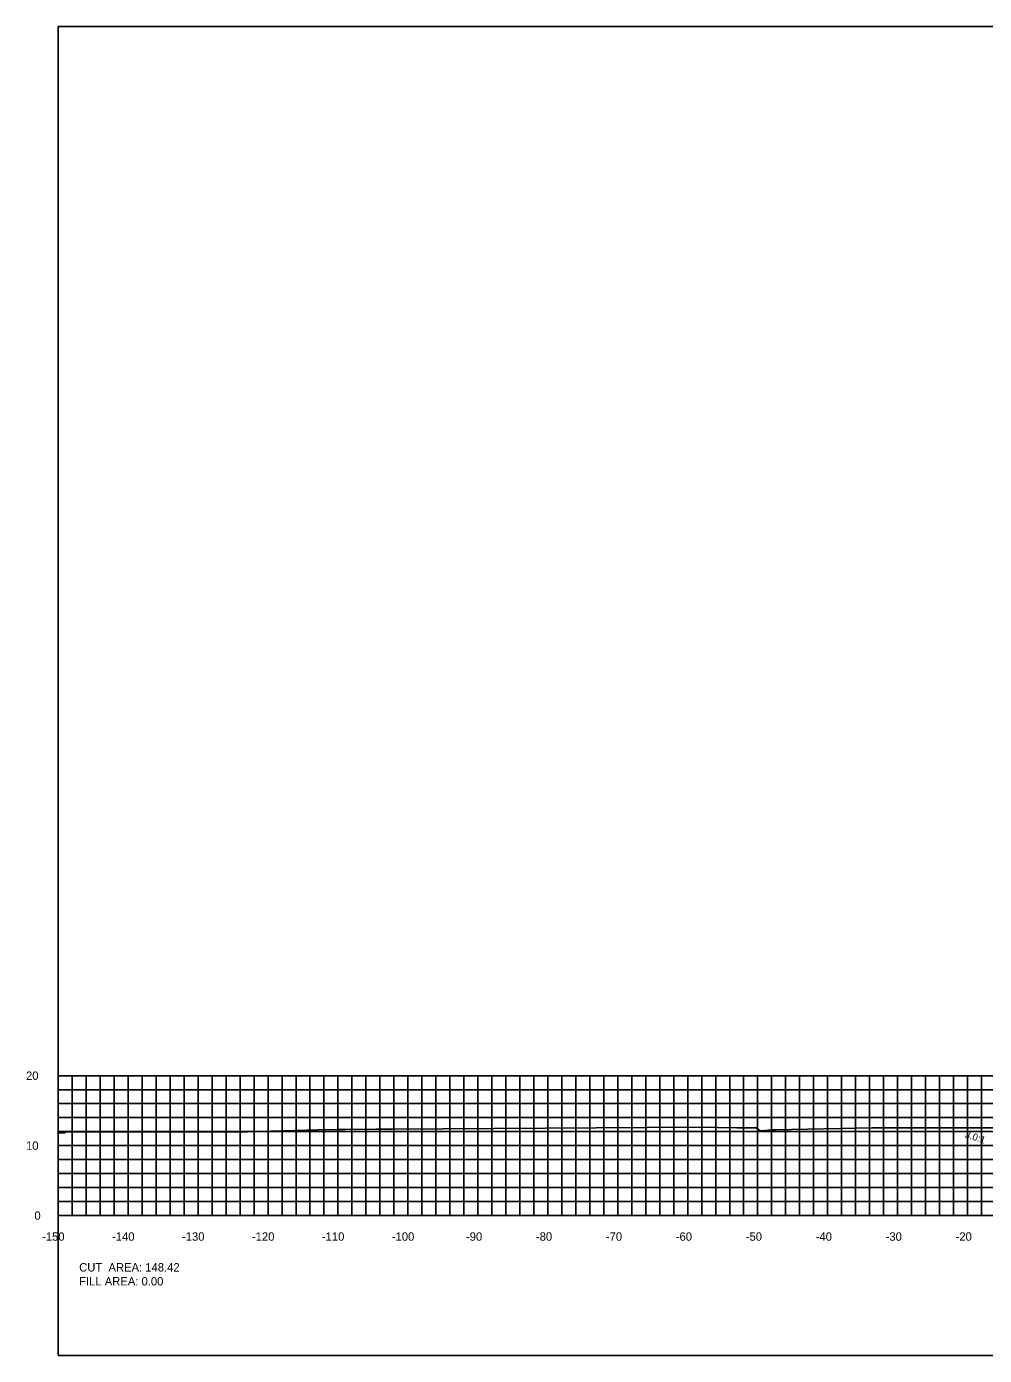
# Model space of a CAD drawing. Extents: x 1800674 to 1802785, y 250079 to 250269.
# Drawn here: x 1802476.5 to 1802613.4, y 250079.4 to 250269.4 of the extents above; entities that cross this region are included whole.
import ezdxf

# ---------------------------------------------------------------- set-up
doc = ezdxf.new("R2010")
doc.units = 0
for name, color, linetype in [('10', 7, 'Continuous'), ('31', 7, 'Continuous'), ('60', 7, 'Continuous'), ('ANNO-TXT', 7, 'Continuous'), ('Level 62', 7, 'Continuous'), ('M-ROADS', 7, 'Continuous')]:
    doc.layers.add(name, color=color, linetype=linetype)

msp = doc.modelspace()

# ---------------------------------------------------------------- linework, layer by layer
msp.add_lwpolyline([(1802481, 250079.43), (1802781, 250079.43), (1802781, 250269.43), (1802481, 250269.43)], close=True)
at = {"layer": '60'}
for p, q in [((1802480.94, 250119.43), (1802481, 250119.43)), ((1802481, 250099.43), (1802481, 250119.43)), ((1802480.94, 250109.43), (1802481, 250109.43)), ((1802480.94, 250099.43), (1802481, 250099.43)), ((1802481, 250099.43), (1802781, 250099.43)), ((1802481, 250099.37), (1802481, 250099.43)), ((1802491, 250099.37), (1802491, 250099.43)), ((1802501, 250099.37), (1802501, 250099.43)), ((1802511, 250099.37), (1802511, 250099.43)), ((1802521, 250099.37), (1802521, 250099.43)), ((1802531, 250099.37), (1802531, 250099.43)), ((1802541, 250099.37), (1802541, 250099.43)), ((1802551, 250099.37), (1802551, 250099.43)), ((1802561, 250099.37), (1802561, 250099.43)), ((1802571, 250099.37), (1802571, 250099.43)), ((1802581, 250099.37), (1802581, 250099.43)), ((1802591, 250099.37), (1802591, 250099.43)), ((1802601, 250099.37), (1802601, 250099.43)), ((1802611, 250099.37), (1802611, 250099.43))]:
    msp.add_line(p, q, dxfattribs=at)
at = {"layer": 'Level 62'}
for p, q in [((1802481, 250119.43), (1802781, 250119.43)), ((1802481, 250099.43), (1802481, 250119.43)), ((1802483, 250099.43), (1802483, 250119.43)), ((1802485, 250099.43), (1802485, 250119.43)), ((1802487, 250099.43), (1802487, 250119.43)), ((1802489, 250099.43), (1802489, 250119.43)), ((1802491, 250099.43), (1802491, 250119.43)), ((1802493, 250099.43), (1802493, 250119.43)), ((1802495, 250099.43), (1802495, 250119.43)), ((1802497, 250099.43), (1802497, 250119.43)), ((1802499, 250099.43), (1802499, 250119.43)), ((1802501, 250099.43), (1802501, 250119.43)), ((1802503, 250099.43), (1802503, 250119.43)), ((1802505, 250099.43), (1802505, 250119.43)), ((1802507, 250099.43), (1802507, 250119.43)), ((1802509, 250099.43), (1802509, 250119.43)), ((1802511, 250099.43), (1802511, 250119.43)), ((1802513, 250099.43), (1802513, 250119.43)), ((1802515, 250099.43), (1802515, 250119.43)), ((1802517, 250099.43), (1802517, 250119.43)), ((1802519, 250099.43), (1802519, 250119.43)), ((1802521, 250099.43), (1802521, 250119.43)), ((1802523, 250099.43), (1802523, 250119.43)), ((1802525, 250099.43), (1802525, 250119.43)), ((1802527, 250099.43), (1802527, 250119.43)), ((1802529, 250099.43), (1802529, 250119.43)), ((1802531, 250099.43), (1802531, 250119.43)), ((1802533, 250099.43), (1802533, 250119.43)), ((1802535, 250099.43), (1802535, 250119.43)), ((1802537, 250099.43), (1802537, 250119.43)), ((1802539, 250099.43), (1802539, 250119.43)), ((1802541, 250099.43), (1802541, 250119.43)), ((1802543, 250099.43), (1802543, 250119.43)), ((1802545, 250099.43), (1802545, 250119.43)), ((1802547, 250099.43), (1802547, 250119.43)), ((1802549, 250099.43), (1802549, 250119.43)), ((1802551, 250099.43), (1802551, 250119.43)), ((1802553, 250099.43), (1802553, 250119.43)), ((1802555, 250099.43), (1802555, 250119.43)), ((1802557, 250099.43), (1802557, 250119.43)), ((1802559, 250099.43), (1802559, 250119.43)), ((1802561, 250099.43), (1802561, 250119.43)), ((1802563, 250099.43), (1802563, 250119.43)), ((1802565, 250099.43), (1802565, 250119.43)), ((1802567, 250099.43), (1802567, 250119.43)), ((1802569, 250099.43), (1802569, 250119.43)), ((1802571, 250099.43), (1802571, 250119.43)), ((1802573, 250099.43), (1802573, 250119.43)), ((1802575, 250099.43), (1802575, 250119.43)), ((1802577, 250099.43), (1802577, 250119.43)), ((1802579, 250099.43), (1802579, 250119.43)), ((1802581, 250099.43), (1802581, 250119.43)), ((1802583, 250099.43), (1802583, 250119.43)), ((1802585, 250099.43), (1802585, 250119.43)), ((1802587, 250099.43), (1802587, 250119.43)), ((1802589, 250099.43), (1802589, 250119.43)), ((1802591, 250099.43), (1802591, 250119.43)), ((1802593, 250099.43), (1802593, 250119.43)), ((1802595, 250099.43), (1802595, 250119.43)), ((1802597, 250099.43), (1802597, 250119.43)), ((1802599, 250099.43), (1802599, 250119.43)), ((1802601, 250099.43), (1802601, 250119.43)), ((1802603, 250099.43), (1802603, 250119.43)), ((1802605, 250099.43), (1802605, 250119.43)), ((1802607, 250099.43), (1802607, 250119.43)), ((1802609, 250099.43), (1802609, 250119.43)), ((1802611, 250099.43), (1802611, 250119.43)), ((1802613, 250099.43), (1802613, 250119.43)), ((1802481, 250117.43), (1802781, 250117.43)), ((1802481, 250115.43), (1802781, 250115.43)), ((1802481, 250113.43), (1802781, 250113.43)), ((1802481, 250111.43), (1802781, 250111.43)), ((1802481, 250109.43), (1802781, 250109.43)), ((1802481, 250107.43), (1802781, 250107.43)), ((1802481, 250105.43), (1802781, 250105.43)), ((1802481, 250103.43), (1802781, 250103.43)), ((1802481, 250101.43), (1802781, 250101.43)), ((1802481, 250099.43), (1802781, 250099.43))]:
    msp.add_line(p, q, dxfattribs=at)
at = {"layer": 'M-ROADS'}
msp.add_lwpolyline([(1802481, 250111.25), (1802481.95, 250111.25), (1802481.96, 250111.27), (1802481.98, 250111.37), (1802482.02, 250111.39), (1802506.39, 250111.36), (1802518.13, 250111.69), (1802521.14, 250111.72), (1802521.97, 250111.73), (1802526.53, 250111.76), (1802527.63, 250111.76), (1802528.75, 250111.77), (1802572.49, 250112.08), (1802578, 250111.95), (1802579.11, 250111.97), (1802579.65, 250111.97), (1802580.22, 250111.98), (1802580.35, 250111.98), (1802580.81, 250111.98), (1802581.19, 250111.67), (1802581.36, 250111.53), (1802581.65, 250111.56), (1802582.95, 250111.68), (1802583.53, 250111.69), (1802597.35, 250111.97), (1802602.79, 250111.96), (1802605.73, 250111.95), (1802608.28, 250111.95), (1802615.38, 250111.95)], dxfattribs=at)

# ---------------------------------------------------------------- texts
msp.add_text('3.0:1', height=1, rotation=341.5651).set_placement((1802610.54, 250110.64))
at = {"layer": '10'}
for s, p in [('-150', (1802478.7, 250095.83)), ('-140', (1802488.7, 250095.83)), ('-130', (1802498.7, 250095.83)), ('-120', (1802508.7, 250095.83)), ('-110', (1802518.7, 250095.83)), ('-100', (1802528.7, 250095.83)), ('-90', (1802539.3, 250095.83)), ('-80', (1802549.3, 250095.83)), ('-70', (1802559.3, 250095.83)), ('-60', (1802569.3, 250095.83)), ('-50', (1802579.3, 250095.83)), ('-40', (1802589.3, 250095.83)), ('-30', (1802599.3, 250095.83)), ('-20', (1802609.3, 250095.83))]:
    msp.add_text(s, height=1.2, dxfattribs=at).set_placement(p)
at = {"layer": '31'}
for s, p in [('20', (1802476.4, 250118.83)), ('10', (1802476.4, 250108.83)), ('0', (1802477.6, 250098.83))]:
    msp.add_text(s, height=1.2, dxfattribs=at).set_placement(p)
at = {"layer": '60'}
msp.add_text('-', height=0.0001, dxfattribs=at).set_placement((1802481, 250099.43))
at = {"layer": 'ANNO-TXT'}
for s, p in [('CUT  AREA: 148.42', (1802484, 250091.43)), ('FILL AREA: 0.00', (1802484, 250089.43))]:
    msp.add_text(s, height=1.2, dxfattribs=at).set_placement(p)

doc.saveas('drawing.dxf')
